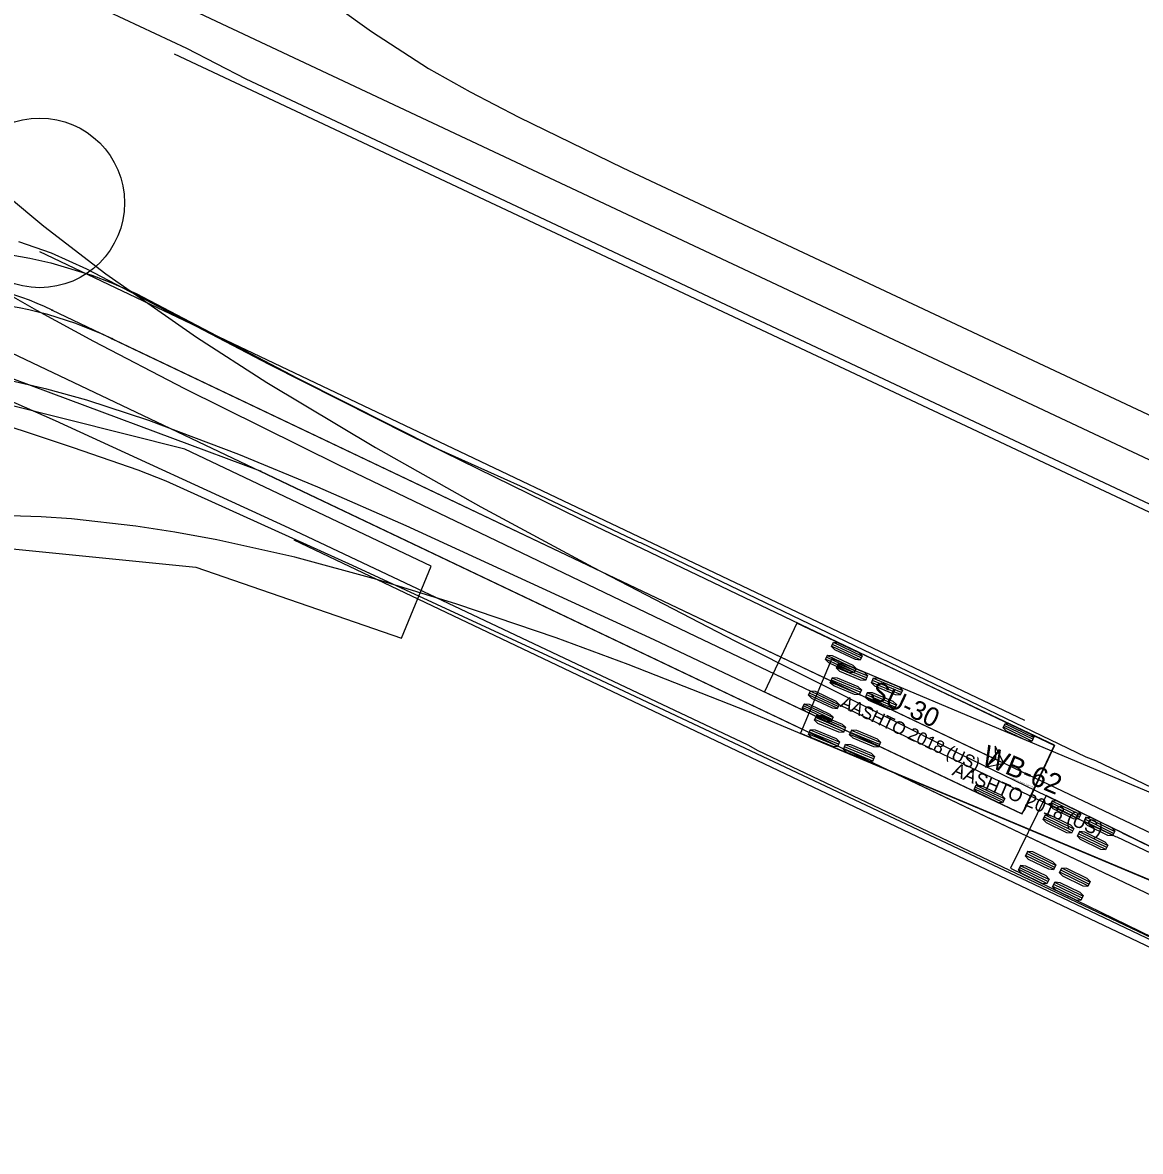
# Model space of a CAD drawing. Extents: x 186128 to 186702, y 352195 to 353183.
# Drawn here: x 186501.6 to 186619.3, y 352841.1 to 352960 of the extents above; entities that cross this region are included whole.
import ezdxf

# ---------------------------------------------------------------- set-up
doc = ezdxf.new("R2010")
doc.units = 0
for name, color, linetype in [('GK_Drainage_Nodes', 7, 'Continuous'), ('SV_X_Control_Cells_Found', 7, 'Continuous'), ('SV_X_Shot_Marker', 7, 'Continuous')]:
    doc.layers.add(name, color=color, linetype=linetype)

msp = doc.modelspace()

# ---------------------------------------------------------------- linework, layer by layer
at = {"layer": 'GK_Drainage_Nodes'}
msp.add_lwpolyline([(186455.99, 352894.17), (186462.66, 352888.85), (186480.45, 352897.88), (186498.71, 352904.75), (186519.8, 352902.65), (186541.45, 352895.17), (186544.58, 352902.76), (186518.65, 352915.08), (186499.81, 352919.82), (186484.74, 352916.37), (186472.96, 352911.19), (186462.32, 352903.52)], close=True, dxfattribs=at)
msp.add_circle((186503.37, 352941), 8.93, dxfattribs=at)
at = {"layer": 'SV_X_Control_Cells_Found'}
for p, q in [((186478.03, 352935.86), (186665.94, 352846.44)), ((186503.35, 352935.88), (186607.04, 352886.53)), ((186504.68, 352929.71), (186604.89, 352882.02)), ((186583.1, 352896.75), (186579.68, 352889.52)), ((186610.22, 352883.92), (186583.1, 352896.75)), ((186589.76, 352892.91), (186586.75, 352894.33)), ((186589.85, 352893.1), (186586.84, 352894.52)), ((186589.94, 352893.29), (186586.93, 352894.71)), ((186589.12, 352891.55), (186586.11, 352892.98)), ((186589.21, 352891.74), (186586.2, 352893.17)), ((186589.3, 352891.93), (186586.29, 352893.35)), ((186579.68, 352889.52), (186606.8, 352876.69)), ((186587.34, 352887.79), (186584.33, 352889.21)), ((186587.43, 352887.97), (186584.42, 352889.4)), ((186587.52, 352888.16), (186584.51, 352889.59)), ((186586.79, 352886.62), (186583.78, 352888.04)), ((186586.88, 352886.81), (186583.86, 352888.23)), ((186586.7, 352886.43), (186583.69, 352887.86)), ((186607.84, 352884.35), (186604.83, 352885.79)), ((186607.93, 352884.54), (186604.92, 352885.97)), ((186608.02, 352884.73), (186605.01, 352886.16)), ((186606.8, 352876.69), (186610.22, 352883.92)), ((186610.22, 352883.92), (186610.22, 352883.92)), ((186604.96, 352878.25), (186601.95, 352879.68)), ((186604.78, 352877.88), (186601.77, 352879.31)), ((186604.87, 352878.06), (186601.86, 352879.5))]:
    msp.add_line(p, q, dxfattribs=at)
for points in [[(186467.42, 352961.58), (186468.24, 352959.38), (186469.81, 352956.17), (186470.89, 352954.43), (186472.08, 352952.79), (186473.39, 352951.15), (186474.8, 352949.61), (186477.46, 352946.95), (186481.13, 352943.8), (186485.89, 352940.22), (186490.68, 352937.01), (186497.6, 352932.78), (186503.05, 352929.69), (186509.05, 352926.44), (186518.63, 352921.46), (186534.9, 352913.39), (186572.4, 352895.37), (186616.63, 352874.31)], [(186501.14, 352936.92), (186504.58, 352935.74), (186508.29, 352934.06), (186527.48, 352924.02), (186542.31, 352916.54), (186560.19, 352907.78), (186583.36, 352896.69)], [(186616.63, 352874.31), (186616.79, 352874.25), (186671.26, 352848.33), (186667.84, 352841.18), (186667.58, 352841.21), (186579.03, 352883.33), (186577.95, 352883.92), (186529.65, 352906.76), (186505.05, 352918.05), (186491.07, 352924.21)], [(186583.36, 352896.69), (186583.52, 352896.63), (186610.23, 352883.87), (186607.11, 352877.24), (186606.75, 352876.68), (186568.07, 352894.99), (186541.95, 352907), (186532.64, 352911.06), (186524.34, 352914.51), (186514.85, 352918.08), (186508.32, 352920.22), (186504.13, 352921.4), (186498.78, 352922.61)], [(186589.96, 352893.33), (186589.74, 352892.86), (186589.25, 352892.92), (186587.08, 352893.95), (186586.73, 352894.29), (186586.95, 352894.76), (186587.44, 352894.7), (186589.61, 352893.67), (186589.96, 352893.33)], [(186589.32, 352891.98), (186589.1, 352891.51), (186588.61, 352891.56), (186586.44, 352892.59), (186586.09, 352892.93), (186586.31, 352893.4), (186586.8, 352893.34), (186588.97, 352892.32), (186589.32, 352891.98)], [(186587.54, 352888.21), (186587.32, 352887.74), (186586.83, 352887.8), (186584.66, 352888.82), (186584.31, 352889.16), (186584.53, 352889.63), (186585.02, 352889.58), (186587.19, 352888.55), (186587.54, 352888.21)], [(186586.9, 352886.85), (186586.68, 352886.38), (186586.19, 352886.44), (186584.02, 352887.47), (186583.66, 352887.81), (186583.89, 352888.28), (186584.38, 352888.22), (186586.55, 352887.19), (186586.9, 352886.85)], [(186608.04, 352884.78), (186607.82, 352884.31), (186607.33, 352884.37), (186605.16, 352885.4), (186604.81, 352885.74), (186605.03, 352886.21), (186605.52, 352886.15), (186607.69, 352885.12), (186608.04, 352884.78)], [(186604.89, 352882.02), (186603.98, 352883.8), (186603.99, 352882.45), (186602.94, 352881.6), (186604.89, 352882.02)], [(186604.98, 352878.3), (186604.75, 352877.83), (186604.27, 352877.89), (186602.1, 352878.92), (186601.74, 352879.26), (186601.97, 352879.73), (186602.46, 352879.67), (186604.62, 352878.64), (186604.98, 352878.3)]]:
    msp.add_lwpolyline(points, dxfattribs=at)
msp.add_lwpolyline([(186604.89, 352882.02), (186603.98, 352883.8), (186603.99, 352882.45), (186602.94, 352881.6)], close=True, dxfattribs=at)
for centre in [(186504.68, 352929.71), (186504.68, 352929.71), (186604.89, 352882.02)]:
    msp.add_circle(centre, 0.0417, dxfattribs=at)
msp.add_arc((186489.64, 352898.11), 35, 64.5505, 154.6637, dxfattribs=at)
at = {"layer": 'SV_X_Shot_Marker'}
for p, q in [((186515.24, 352963.3), (186641.2, 352904.08)), ((186517.52, 352956.7), (186639.07, 352899.56)), ((186526.61, 352912.75), (186486.06, 352927.85)), ((186511.01, 352926.7), (186644.66, 352863.09)), ((186526.61, 352912.75), (186665.94, 352846.44)), ((186530.14, 352905.53), (186663.79, 352841.93)), ((186586.76, 352893.03), (186583.46, 352885.19)), ((186631, 352874.42), (186586.76, 352893.03)), ((186590.32, 352890.79), (186587.28, 352892.06)), ((186590.41, 352891), (186587.37, 352892.28)), ((186590.5, 352891.21), (186587.45, 352892.49)), ((186589.68, 352889.26), (186586.64, 352890.54)), ((186589.77, 352889.48), (186586.73, 352890.76)), ((186589.86, 352889.69), (186586.81, 352890.97)), ((186594.01, 352889.23), (186590.96, 352890.51)), ((186594.09, 352889.45), (186591.05, 352890.73)), ((186594.18, 352889.66), (186591.14, 352890.94)), ((186593.45, 352887.92), (186590.41, 352889.2)), ((186593.54, 352888.14), (186590.5, 352889.42)), ((186593.37, 352887.71), (186590.32, 352888.99)), ((186588.11, 352885.53), (186585.06, 352886.81)), ((186588.2, 352885.74), (186585.15, 352887.02)), ((186588.02, 352885.32), (186584.98, 352886.6)), ((186583.46, 352885.19), (186627.71, 352866.58)), ((186587.38, 352883.8), (186584.34, 352885.07)), ((186587.47, 352884.01), (186584.43, 352885.29)), ((186587.56, 352884.22), (186584.51, 352885.5)), ((186591.7, 352883.77), (186588.66, 352885.04)), ((186591.79, 352883.98), (186588.75, 352885.26)), ((186591.88, 352884.19), (186588.84, 352885.47)), ((186591.07, 352882.24), (186588.02, 352883.52)), ((186591.15, 352882.46), (186588.11, 352883.74)), ((186591.24, 352882.67), (186588.2, 352883.95)), ((186609.32, 352878.61), (186605.58, 352870.97)), ((186652.44, 352857.54), (186609.32, 352878.61)), ((186612.74, 352876.17), (186609.78, 352877.62)), ((186612.84, 352876.38), (186609.88, 352877.83)), ((186612.94, 352876.58), (186609.98, 352878.03)), ((186612.02, 352874.69), (186609.05, 352876.14)), ((186612.12, 352874.9), (186609.15, 352876.34)), ((186612.22, 352875.1), (186609.25, 352876.55)), ((186616.44, 352874.62), (186613.47, 352876.07)), ((186616.54, 352874.83), (186613.57, 352876.28)), ((186616.34, 352874.42), (186613.37, 352875.87)), ((186615.61, 352872.93), (186612.65, 352874.38)), ((186615.71, 352873.14), (186612.75, 352874.59)), ((186615.81, 352873.35), (186612.85, 352874.79)), ((186610.24, 352871.05), (186607.27, 352872.5)), ((186610.34, 352871.25), (186607.37, 352872.7)), ((186610.14, 352870.84), (186607.17, 352872.29)), ((186605.58, 352870.97), (186648.71, 352849.9)), ((186609.41, 352869.36), (186606.45, 352870.81)), ((186609.51, 352869.56), (186606.55, 352871.01)), ((186609.61, 352869.77), (186606.65, 352871.22)), ((186613.73, 352869.09), (186610.77, 352870.53)), ((186613.83, 352869.29), (186610.87, 352870.74)), ((186613.93, 352869.5), (186610.97, 352870.95)), ((186613.01, 352867.6), (186610.04, 352869.05)), ((186613.11, 352867.81), (186610.14, 352869.26)), ((186613.21, 352868.01), (186610.24, 352869.46))]:
    msp.add_line(p, q, dxfattribs=at)
for points in [[(186481.11, 352963.55), (186483.34, 352959.94), (186486.82, 352955.15), (186491.18, 352950.13), (186496.89, 352944.49), (186499.97, 352941.73), (186503.81, 352938.55), (186510.34, 352933.53), (186519.89, 352926.87), (186527.3, 352922.08), (186538.72, 352915.26), (186549.81, 352909.02), (186561.62, 352902.66), (186576.55, 352894.88), (186600.33, 352882.97), (186617.33, 352874.71)], [(186649.38, 352904.96), (186649.54, 352904.86), (186701.84, 352880.29), (186698.49, 352873.1), (186698.16, 352872.61), (186525.1, 352954.01), (186518.86, 352957.26), (186508.96, 352961.88)], [(186534.71, 352961.62), (186538.29, 352959.03), (186544.32, 352955.16), (186548.69, 352952.7), (186553.81, 352950.01), (186564.76, 352944.69), (186649.38, 352904.96)], [(186499.78, 352935.62), (186502.33, 352935.19), (186504.53, 352934.7), (186508.86, 352933.38), (186510.86, 352932.63), (186513.52, 352931.45), (186530.52, 352922.56), (186545.35, 352915.08), (186553.94, 352911.21), (186566.44, 352905.27)], [(186617.33, 352874.71), (186617.49, 352874.61), (186651.78, 352857.87), (186652.43, 352857.55), (186652.33, 352857.38), (186652.4, 352857.28), (186653.45, 352856.76), (186671.26, 352848.33), (186668.25, 352841.96), (186667.85, 352841.18), (186667.75, 352841.14), (186648.92, 352850.13), (186648.79, 352850.16), (186648.69, 352849.9), (186648.46, 352850), (186607.39, 352869.55), (186562.47, 352890.72), (186536.32, 352902.82), (186516.67, 352911.71), (186513.75, 352912.86), (186506.93, 352915.22), (186484.29, 352922.74)], [(186627.37, 352866.69), (186577.93, 352887.45), (186565.33, 352892.41), (186557.75, 352895.2), (186547.28, 352898.77), (186538.85, 352901.36), (186530.22, 352903.69), (186522.02, 352905.53), (186517.59, 352906.35), (186513.49, 352906.97), (186506.7, 352907.73), (186503.52, 352907.96), (186499.12, 352908.09)], [(186566.44, 352905.27), (186566.61, 352905.24), (186613.52, 352882.7), (186614.54, 352882.3), (186630.65, 352874.59)], [(186590.52, 352891.26), (186590.3, 352890.73), (186589.8, 352890.75), (186587.61, 352891.67), (186587.25, 352892.01), (186587.48, 352892.54), (186587.97, 352892.52), (186590.16, 352891.6), (186590.52, 352891.26)], [(186589.88, 352889.74), (186589.66, 352889.21), (186589.16, 352889.23), (186586.97, 352890.15), (186586.61, 352890.49), (186586.84, 352891.02), (186587.33, 352891), (186589.52, 352890.08), (186589.88, 352889.74)], [(186594.21, 352889.71), (186593.98, 352889.18), (186593.49, 352889.2), (186591.3, 352890.12), (186590.94, 352890.46), (186591.16, 352890.99), (186591.66, 352890.97), (186593.85, 352890.05), (186594.21, 352889.71)], [(186593.57, 352888.19), (186593.34, 352887.66), (186592.85, 352887.68), (186590.66, 352888.6), (186590.3, 352888.94), (186590.52, 352889.47), (186591.02, 352889.45), (186593.21, 352888.53), (186593.57, 352888.19)], [(186588.22, 352885.79), (186588, 352885.26), (186587.5, 352885.28), (186585.31, 352886.21), (186584.95, 352886.54), (186585.18, 352887.07), (186585.67, 352887.05), (186587.86, 352886.13), (186588.22, 352885.79)], [(186587.58, 352884.27), (186587.36, 352883.74), (186586.86, 352883.76), (186584.67, 352884.68), (186584.31, 352885.02), (186584.54, 352885.55), (186585.03, 352885.53), (186587.22, 352884.61), (186587.58, 352884.27)], [(186591.9, 352884.24), (186591.68, 352883.71), (186591.19, 352883.73), (186589, 352884.65), (186588.64, 352884.99), (186588.86, 352885.52), (186589.36, 352885.5), (186591.55, 352884.58), (186591.9, 352884.24)], [(186591.26, 352882.72), (186591.04, 352882.19), (186590.55, 352882.21), (186588.36, 352883.13), (186588, 352883.47), (186588.22, 352884), (186588.72, 352883.98), (186590.91, 352883.06), (186591.26, 352882.72)], [(186612.97, 352876.64), (186612.72, 352876.12), (186612.23, 352876.17), (186610.09, 352877.21), (186609.75, 352877.57), (186610, 352878.08), (186610.49, 352878.04), (186612.63, 352876.99), (186612.97, 352876.64)], [(186612.24, 352875.15), (186611.99, 352874.64), (186611.5, 352874.69), (186609.37, 352875.73), (186609.03, 352876.09), (186609.28, 352876.6), (186609.77, 352876.55), (186611.9, 352875.51), (186612.24, 352875.15)], [(186616.56, 352874.88), (186616.31, 352874.37), (186615.82, 352874.41), (186613.69, 352875.46), (186613.35, 352875.81), (186613.6, 352876.33), (186614.09, 352876.28), (186616.22, 352875.24), (186616.56, 352874.88)], [(186615.84, 352873.4), (186615.59, 352872.88), (186615.1, 352872.93), (186612.96, 352873.97), (186612.62, 352874.33), (186612.87, 352874.85), (186613.36, 352874.8), (186615.5, 352873.75), (186615.84, 352873.4)], [(186610.36, 352871.3), (186610.11, 352870.79), (186609.62, 352870.84), (186607.49, 352871.88), (186607.15, 352872.24), (186607.4, 352872.75), (186607.89, 352872.7), (186610.02, 352871.66), (186610.36, 352871.3)], [(186609.64, 352869.82), (186609.39, 352869.31), (186608.9, 352869.36), (186606.76, 352870.4), (186606.42, 352870.76), (186606.67, 352871.27), (186607.17, 352871.22), (186609.3, 352870.18), (186609.64, 352869.82)], [(186613.96, 352869.55), (186613.71, 352869.03), (186613.22, 352869.08), (186611.08, 352870.13), (186610.74, 352870.48), (186610.99, 352871), (186611.48, 352870.95), (186613.62, 352869.91), (186613.96, 352869.55)], [(186613.23, 352868.07), (186612.98, 352867.55), (186612.49, 352867.6), (186610.36, 352868.64), (186610.02, 352869), (186610.27, 352869.51), (186610.76, 352869.47), (186612.89, 352868.42), (186613.23, 352868.07)]]:
    msp.add_lwpolyline(points, dxfattribs=at)
for centre in [(186511.01, 352926.7), (186511.01, 352926.7), (186526.61, 352912.75), (186526.61, 352912.75)]:
    msp.add_circle(centre, 0.0417, dxfattribs=at)
msp.add_arc((186492.96, 352888.77), 42, 64.5505, 154.6637, dxfattribs=at)

# ---------------------------------------------------------------- texts
at = {"layer": 'SV_X_Control_Cells_Found'}
for s, height, p in [('SU-30', 2, (186590.63, 352888.94)), ('AASHTO 2018 (US)', 1.3333, (186587.57, 352887.99)), ('(c) 2025 Transoft Solutions, Inc. All rights reserved.', 0.08, (186593.45, 352887.39))]:
    msp.add_text(s, height=height, rotation=334.6838, dxfattribs=at).set_placement(p)
at = {"layer": 'SV_X_Shot_Marker'}
for s, height, p in [('WB-62', 2.125, (186602.4, 352882.02)), ('AASHTO 2018 (US)', 1.4167, (186599.34, 352880.81)), ('(c) 2025 Transoft Solutions, Inc. All rights reserved.', 0.085, (186605.61, 352880.44))]:
    msp.add_text(s, height=height, rotation=337.185, dxfattribs=at).set_placement(p)

doc.saveas('drawing.dxf')
